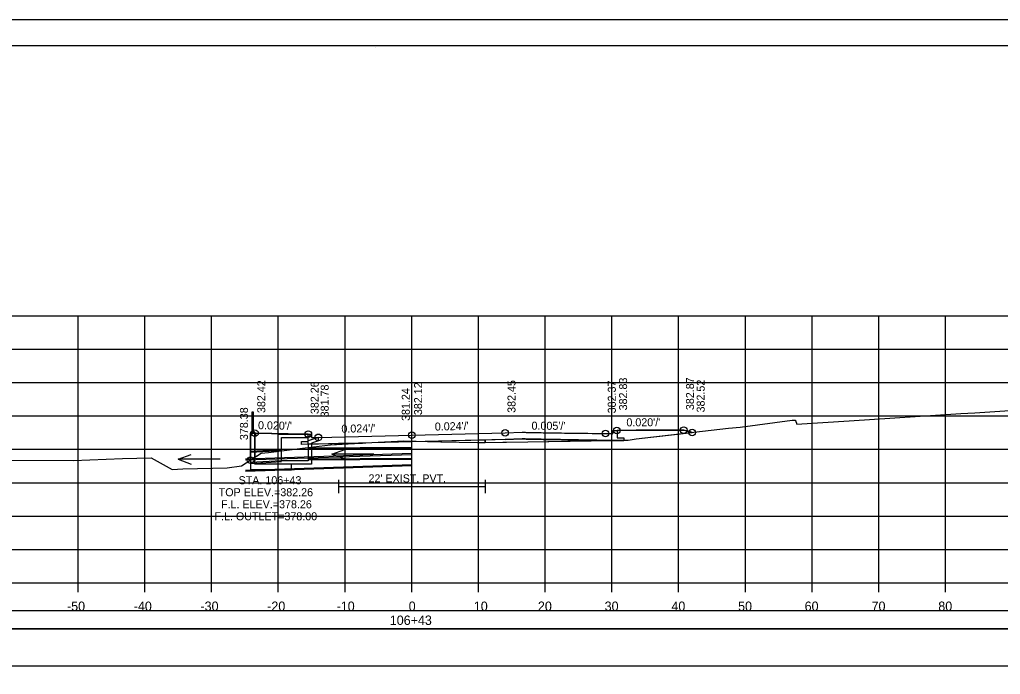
# Model space of a CAD drawing. Extents: x -37291014 to -37290680, y -936053 to -933067.
# Drawn here: x -37290901.9 to -37290754.9, y -934658 to -934559.9 of the extents above; entities that cross this region are included whole.
import ezdxf

# ---------------------------------------------------------------- set-up
doc = ezdxf.new("R2010")
doc.units = 0
for name, color, linetype in [('Default', 7, 'Continuous'), ('R_Alt Surface', 7, 'Continuous'), ('R_Axis', 7, 'Continuous'), ('R_Axis Annot', 7, 'Continuous'), ('R_Border', 7, 'Continuous'), ('R_Contours', 7, 'Continuous'), ('R_Exist Surface', 7, 'Continuous'), ('R_Fin Surface', 7, 'Continuous'), ('R_Grid', 7, 'Continuous'), ('R_No Plot', 7, 'Continuous'), ('R_Water', 7, 'Continuous'), ('R_Water Annot', 7, 'Continuous'), ('R_Xsect Elev', 7, 'Continuous'), ('R_Xsect Slope', 7, 'Continuous')]:
    doc.layers.add(name, color=color, linetype=linetype)

msp = doc.modelspace()

# ---------------------------------------------------------------- linework, layer by layer
at = {"layer": 'Default'}
for p, q in [((-37290867.02, -934621.69), (-37290867.02, -934618.69)), ((-37290867.02, -934618.69), (-37290866.85, -934618.69)), ((-37290866.85, -934618.69), (-37290866.85, -934621.69)), ((-37290867.21, -934621.71), (-37290867.27, -934621.77)), ((-37290867.27, -934621.77), (-37290867.27, -934627.37)), ((-37290866.66, -934621.69), (-37290867.21, -934621.69)), ((-37290867.21, -934621.69), (-37290867.21, -934621.71)), ((-37290866.66, -934621.71), (-37290867.21, -934621.71)), ((-37290866.66, -934621.71), (-37290866.66, -934621.69)), ((-37290866.6, -934621.77), (-37290866.66, -934621.71)), ((-37290866.6, -934626.54), (-37290866.6, -934621.77)), ((-37290861.1, -934626.54), (-37290866.6, -934626.54)), ((-37290861.1, -934627.37), (-37290861.1, -934626.54)), ((-37290861.1, -934627.37), (-37290867.27, -934627.37))]:
    msp.add_line(p, q, dxfattribs=at)
msp.add_lwpolyline([(-37290866.52, -934622.37), (-37290866.6, -934622.37), (-37290866.6, -934621.87), (-37290866.52, -934621.87), (-37290866.52, -934622.37)], dxfattribs=at)
for points in [[(-37290992.31, -934651.2), (-37290693.89, -934651.2), (-37290693.89, -934648.5), (-37290992.31, -934648.5)], [(-37290992.31, -934656.72), (-37290693.89, -934656.72), (-37290693.89, -934651.2), (-37290992.31, -934651.2)]]:
    msp.add_lwpolyline(points, close=True, dxfattribs=at)
at = {"layer": 'R_Alt Surface'}
for points in [[(-37290829.1, -934622.84), (-37290843.1, -934623.18), (-37290857.1, -934623.51), (-37290858.6, -934623.54), (-37290859.6, -934623.56), (-37290859.61, -934623.15), (-37290858.6, -934623.13), (-37290858.6, -934622.03)], [(-37290812.34, -934621.47), (-37290812.34, -934622.56), (-37290811.33, -934622.58), (-37290811.34, -934623), (-37290815.35, -934622.92)], [(-37290829.1, -934622.84), (-37290826.57, -934622.74), (-37290826.32, -934622.75), (-37290826.11, -934622.75), (-37290826.1, -934622.75), (-37290825.93, -934622.76), (-37290825.84, -934622.76), (-37290825.81, -934622.76), (-37290825.54, -934622.77), (-37290825.49, -934622.77), (-37290825.38, -934622.77), (-37290825.2, -934622.77), (-37290825.01, -934622.78), (-37290824.82, -934622.78), (-37290824.59, -934622.79), (-37290824.49, -934622.79), (-37290824.4, -934622.79), (-37290823.93, -934622.8), (-37290823.92, -934622.8), (-37290823.72, -934622.8), (-37290823.69, -934622.8), (-37290823.41, -934622.81), (-37290823.29, -934622.81), (-37290822.84, -934622.82), (-37290822.78, -934622.82), (-37290822.61, -934622.82), (-37290822.22, -934622.83), (-37290821.88, -934622.84), (-37290821.76, -934622.84), (-37290821.54, -934622.84), (-37290821.43, -934622.84), (-37290821.08, -934622.85), (-37290820.8, -934622.85), (-37290820.64, -934622.86), (-37290820.23, -934622.86), (-37290819.99, -934622.86), (-37290819.43, -934622.87), (-37290819.3, -934622.87), (-37290819.1, -934622.88), (-37290818.3, -934622.88), (-37290818.15, -934622.89), (-37290818.12, -934622.89), (-37290815.35, -934622.92)], [(-37290854.1, -934628.85), (-37290854.1, -934630.85)], [(-37290832.1, -934628.85), (-37290832.1, -934630.85)], [(-37290854.1, -934629.85), (-37290832.1, -934629.85)]]:
    msp.add_lwpolyline(points, dxfattribs=at)
at = {"layer": 'R_Axis'}
for p, q in [((-37290993.1, -934644.3), (-37290693.1, -934644.3)), ((-37290893.1, -934645.7), (-37290893.1, -934644.3)), ((-37290883.1, -934645.7), (-37290883.1, -934644.3)), ((-37290873.1, -934645.7), (-37290873.1, -934644.3)), ((-37290863.1, -934645.7), (-37290863.1, -934644.3)), ((-37290853.1, -934645.7), (-37290853.1, -934644.3)), ((-37290843.1, -934645.7), (-37290843.1, -934644.3)), ((-37290833.1, -934645.7), (-37290833.1, -934644.3)), ((-37290823.1, -934645.7), (-37290823.1, -934644.3)), ((-37290813.1, -934645.7), (-37290813.1, -934644.3)), ((-37290803.1, -934645.7), (-37290803.1, -934644.3)), ((-37290793.1, -934645.7), (-37290793.1, -934644.3)), ((-37290783.1, -934645.7), (-37290783.1, -934644.3)), ((-37290773.1, -934645.7), (-37290773.1, -934644.3)), ((-37290763.1, -934645.7), (-37290763.1, -934644.3))]:
    msp.add_line(p, q, dxfattribs=at)
at = {"layer": 'R_Border'}
for p, q in [((-37291001.1, -934563.84), (-37290684.92, -934563.84)), ((-37290848.58, -934564.1), (-37290848.58, -934564.1)), ((-37290848.58, -934564.1), (-37290848.58, -934564.1))]:
    msp.add_line(p, q, dxfattribs=at)
at = {"layer": 'R_Contours'}
for p, q in [((-37290801.07, -934621.78), (-37290801.35, -934621.7)), ((-37290866.6, -934622.37), (-37290866.6, -934625.48)), ((-37290854.1, -934623.55), (-37290850.5, -934623.36)), ((-37290850.5, -934623.36), (-37290854.1, -934623.44)), ((-37290854.1, -934623.44), (-37290854.1, -934623.55)), ((-37290854.1, -934623.55), (-37290854.1, -934623.44)), ((-37290832.1, -934622.91), (-37290840.74, -934623.12)), ((-37290829.1, -934622.84), (-37290832.1, -934622.91)), ((-37290832.1, -934623.26), (-37290832.1, -934622.91)), ((-37290832.1, -934622.91), (-37290832.1, -934623.26)), ((-37290813.02, -934622.96), (-37290815.35, -934622.92)), ((-37290811.34, -934622.93), (-37290813.02, -934622.96)), ((-37290813.02, -934622.96), (-37290811.34, -934623)), ((-37290811.34, -934623), (-37290811.34, -934622.93)), ((-37290866.6, -934625.48), (-37290867.27, -934625.91)), ((-37290866.6, -934626.54), (-37290866.6, -934625.48)), ((-37290861.1, -934626.54), (-37290866.6, -934626.54)), ((-37290861.1, -934627.37), (-37290861.1, -934626.54)), ((-37290867.27, -934627.37), (-37290861.1, -934627.37))]:
    msp.add_line(p, q, dxfattribs=at)
for points in [[(-37290866.52, -934621.88), (-37290866.52, -934622.37), (-37290866.6, -934622.37)], [(-37290858.6, -934622.03), (-37290861.6, -934621.97), (-37290866.52, -934621.88)], [(-37290854.1, -934623.44), (-37290857.1, -934623.51), (-37290858.6, -934623.54), (-37290859.6, -934623.56), (-37290859.61, -934623.15), (-37290858.6, -934623.13), (-37290858.6, -934622.03)], [(-37290801.35, -934621.7), (-37290802.35, -934621.43), (-37290802.42, -934621.43), (-37290802.43, -934621.43), (-37290803.95, -934621.43), (-37290804.11, -934621.43), (-37290804.4, -934621.43), (-37290804.44, -934621.44), (-37290806.18, -934621.44), (-37290807.2, -934621.45), (-37290807.64, -934621.45), (-37290807.73, -934621.45), (-37290808.2, -934621.45), (-37290808.31, -934621.45), (-37290809.47, -934621.45), (-37290812.15, -934621.47), (-37290812.26, -934621.47), (-37290812.34, -934621.47)], [(-37290812.34, -934621.47), (-37290812.34, -934622.56), (-37290811.33, -934622.58), (-37290811.34, -934622.93)], [(-37290811.34, -934622.93), (-37290810.65, -934622.92), (-37290809.45, -934622.75), (-37290801.07, -934621.78)], [(-37290866.6, -934625.48), (-37290865.67, -934624.87), (-37290864.57, -934624.78), (-37290859.46, -934624.13), (-37290857.83, -934623.95), (-37290855.28, -934623.61), (-37290854.1, -934623.55)], [(-37290840.74, -934623.12), (-37290838.72, -934623.18), (-37290833.25, -934623.27), (-37290832.1, -934623.26)], [(-37290832.1, -934623.26), (-37290825.72, -934623.2), (-37290813.02, -934622.96)], [(-37290815.35, -934622.92), (-37290818.12, -934622.89), (-37290818.15, -934622.89), (-37290818.3, -934622.88), (-37290819.1, -934622.88), (-37290819.3, -934622.87), (-37290819.43, -934622.87), (-37290819.99, -934622.86), (-37290820.23, -934622.86), (-37290820.64, -934622.86), (-37290820.8, -934622.85), (-37290821.08, -934622.85), (-37290821.43, -934622.84), (-37290821.54, -934622.84), (-37290821.76, -934622.84), (-37290821.88, -934622.84), (-37290822.22, -934622.83), (-37290822.61, -934622.82), (-37290822.78, -934622.82), (-37290822.84, -934622.82), (-37290823.29, -934622.81), (-37290823.41, -934622.81), (-37290823.69, -934622.8), (-37290823.72, -934622.8), (-37290823.92, -934622.8), (-37290823.93, -934622.8), (-37290824.4, -934622.79), (-37290824.49, -934622.79), (-37290824.59, -934622.79), (-37290824.82, -934622.78), (-37290825.01, -934622.78), (-37290825.2, -934622.77), (-37290825.38, -934622.77), (-37290825.49, -934622.77), (-37290825.54, -934622.77), (-37290825.81, -934622.76), (-37290825.84, -934622.76), (-37290825.93, -934622.76), (-37290826.11, -934622.75), (-37290826.32, -934622.75), (-37290826.57, -934622.74), (-37290829.1, -934622.84)], [(-37290867.27, -934625.91), (-37290867.27, -934625.92), (-37290867.27, -934627.37)]]:
    msp.add_lwpolyline(points, dxfattribs=at)
at = {"layer": 'R_Exist Surface'}
msp.add_lwpolyline([(-37290905.12, -934625.95), (-37290893.8, -934626), (-37290886.47, -934625.67), (-37290882.14, -934625.59), (-37290878.99, -934627.3), (-37290877.42, -934627.24), (-37290870.76, -934627.09), (-37290868.6, -934626.78), (-37290865.67, -934624.87), (-37290864.57, -934624.78), (-37290859.46, -934624.13), (-37290857.83, -934623.95), (-37290855.28, -934623.61), (-37290849.08, -934623.28), (-37290844.28, -934623.02), (-37290838.72, -934623.18), (-37290833.25, -934623.27), (-37290825.72, -934623.2), (-37290810.65, -934622.92), (-37290809.45, -934622.75), (-37290795.65, -934621.15), (-37290793.87, -934620.98), (-37290786.08, -934619.94), (-37290786.05, -934619.94), (-37290785.6, -934619.95), (-37290785.59, -934619.97), (-37290785.4, -934620.51), (-37290784.63, -934620.46), (-37290777.56, -934620.01), (-37290760.79, -934618.95), (-37290758.73, -934618.83), (-37290731.11, -934617.01)], dxfattribs=at)
at = {"layer": 'R_Fin Surface'}
for points in [[(-37290867.27, -934625.92), (-37290867.27, -934621.87), (-37290866.6, -934621.87), (-37290861.6, -934621.97), (-37290858.6, -934622.03), (-37290858.1, -934622.03), (-37290858.1, -934622.53), (-37290857.1, -934622.51), (-37290843.1, -934622.18), (-37290829.1, -934621.84)], [(-37290829.1, -934621.84), (-37290826.57, -934621.74), (-37290826.32, -934621.75), (-37290826.11, -934621.75), (-37290826.1, -934621.75), (-37290825.93, -934621.76), (-37290825.84, -934621.76), (-37290825.82, -934621.76), (-37290825.54, -934621.77), (-37290825.49, -934621.77), (-37290825.38, -934621.77), (-37290825.2, -934621.77), (-37290825.01, -934621.78), (-37290824.82, -934621.78), (-37290824.59, -934621.79), (-37290824.49, -934621.79), (-37290824.4, -934621.79), (-37290823.93, -934621.8), (-37290823.92, -934621.8), (-37290823.72, -934621.8), (-37290823.7, -934621.8), (-37290823.41, -934621.81), (-37290823.29, -934621.81), (-37290822.84, -934621.82), (-37290822.78, -934621.82), (-37290822.61, -934621.82), (-37290822.22, -934621.83), (-37290821.88, -934621.84), (-37290821.76, -934621.84), (-37290821.54, -934621.84), (-37290821.43, -934621.84), (-37290821.09, -934621.85), (-37290820.8, -934621.85), (-37290820.64, -934621.85), (-37290820.23, -934621.86), (-37290819.99, -934621.86), (-37290819.44, -934621.87), (-37290819.3, -934621.87), (-37290819.11, -934621.88), (-37290818.3, -934621.88), (-37290818.15, -934621.89), (-37290818.12, -934621.89), (-37290817.23, -934621.9), (-37290817.11, -934621.9), (-37290816.7, -934621.9), (-37290816.08, -934621.91), (-37290815.98, -934621.91), (-37290815.92, -934621.91), (-37290815.16, -934621.92), (-37290814.84, -934621.92), (-37290814.77, -934621.92), (-37290814.07, -934621.92), (-37290813.19, -934621.95), (-37290812.95, -934621.96), (-37290812.94, -934621.54), (-37290812.94, -934621.46), (-37290812.39, -934621.47), (-37290812.38, -934621.47), (-37290812.34, -934621.47), (-37290812.34, -934621.47), (-37290812.26, -934621.47), (-37290812.15, -934621.47), (-37290812.14, -934621.47), (-37290809.47, -934621.45), (-37290808.31, -934621.45), (-37290808.2, -934621.45), (-37290807.73, -934621.45), (-37290807.64, -934621.45), (-37290807.2, -934621.45), (-37290806.18, -934621.44), (-37290804.44, -934621.44), (-37290804.4, -934621.43), (-37290804.11, -934621.43), (-37290803.95, -934621.43), (-37290802.43, -934621.43), (-37290802.42, -934621.43), (-37290802.42, -934621.43), (-37290802.42, -934621.43), (-37290802.35, -934621.43), (-37290801.35, -934621.7), (-37290801.07, -934621.78)]]:
    msp.add_lwpolyline(points, dxfattribs=at)
at = {"layer": 'R_Grid'}
for p, q in [((-37290993.1, -934604.3), (-37290693.1, -934604.3)), ((-37290893.1, -934644.3), (-37290893.1, -934604.3)), ((-37290883.1, -934644.3), (-37290883.1, -934604.3)), ((-37290873.1, -934644.3), (-37290873.1, -934604.3)), ((-37290863.1, -934644.3), (-37290863.1, -934604.3)), ((-37290853.1, -934644.3), (-37290853.1, -934604.3)), ((-37290843.1, -934644.3), (-37290843.1, -934604.3)), ((-37290833.1, -934644.3), (-37290833.1, -934604.3)), ((-37290823.1, -934644.3), (-37290823.1, -934604.3)), ((-37290813.1, -934644.3), (-37290813.1, -934604.3)), ((-37290803.1, -934644.3), (-37290803.1, -934604.3)), ((-37290793.1, -934644.3), (-37290793.1, -934604.3)), ((-37290783.1, -934644.3), (-37290783.1, -934604.3)), ((-37290773.1, -934644.3), (-37290773.1, -934604.3)), ((-37290763.1, -934644.3), (-37290763.1, -934604.3)), ((-37290993.1, -934609.3), (-37290693.1, -934609.3)), ((-37290993.1, -934614.3), (-37290693.1, -934614.3)), ((-37290993.1, -934619.3), (-37290693.1, -934619.3)), ((-37290993.1, -934624.3), (-37290693.1, -934624.3)), ((-37290993.1, -934629.3), (-37290693.1, -934629.3)), ((-37290993.1, -934634.3), (-37290693.1, -934634.3)), ((-37290993.1, -934639.3), (-37290693.1, -934639.3)), ((-37290993.1, -934644.3), (-37290693.1, -934644.3))]:
    msp.add_line(p, q, dxfattribs=at)
at = {"layer": 'R_No Plot'}
for p, q in [((-37291013.5, -934559.94), (-37290680.17, -934559.94)), ((-37290843.1, -934624.94), (-37290868.02, -934625.78)), ((-37290862.6, -934624.37), (-37290867.27, -934624.63)), ((-37290843.1, -934624.02), (-37290858.61, -934624.12)), ((-37290862.6, -934626.2), (-37290867.27, -934626.46)), ((-37290843.1, -934625.85), (-37290858.61, -934625.95)), ((-37290843.1, -934626.77), (-37290868.02, -934627.62))]:
    msp.add_line(p, q, dxfattribs=at)
for points in [[(-37291013.51, -934559.94), (-37290680.17, -934559.94), (-37290680.17, -934773.28), (-37291013.51, -934773.28)], [(-37290767.18, -934563.84), (-37290747.56, -934563.84), (-37290747.56, -934573.72), (-37290731.45, -934573.72), (-37290708.25, -934573.72), (-37290708.25, -934598.05), (-37290684.92, -934598.05), (-37290684.92, -934769.3), (-37291001.1, -934769.3), (-37291001.1, -934563.84)]]:
    msp.add_lwpolyline(points, close=True, dxfattribs=at)
for centre in [(-37290866.6, -934621.87), (-37290858.6, -934622.03), (-37290857.1, -934622.51), (-37290843.1, -934622.18), (-37290829.1, -934621.84), (-37290829.1, -934621.84), (-37290814.07, -934621.92), (-37290812.38, -934621.47), (-37290802.35, -934621.43), (-37290801.07, -934621.78), (-37290867.27, -934625.92)]:
    msp.add_circle(centre, 0.5, dxfattribs=at)
at = {"layer": 'R_Water'}
for p, q in [((-37290863.1, -934622.03), (-37290858.35, -934622.03)), ((-37290863.1, -934623.53), (-37290863.1, -934622.03)), ((-37290858.27, -934622.2), (-37290858.6, -934622.53)), ((-37290858.27, -934622.2), (-37290858.35, -934622.03)), ((-37290862.6, -934623.53), (-37290862.6, -934622.53)), ((-37290862.6, -934622.53), (-37290858.6, -934622.53)), ((-37290857.1, -934622.51), (-37290858.6, -934623.03)), ((-37290858.6, -934623.53), (-37290858.6, -934623.03)), ((-37290857.1, -934623.04), (-37290858.1, -934623.39)), ((-37290858.1, -934623.53), (-37290858.1, -934623.39)), ((-37290843.1, -934625.11), (-37290868.02, -934625.95)), ((-37290862.6, -934624.54), (-37290867.27, -934624.8)), ((-37290843.1, -934624.19), (-37290858.61, -934624.29)), ((-37290843.1, -934626.61), (-37290868.02, -934627.45)), ((-37290862.6, -934626.04), (-37290867.27, -934626.3)), ((-37290843.1, -934625.69), (-37290858.61, -934625.79))]:
    msp.add_line(p, q, dxfattribs=at)
for points in [[(-37290858.1, -934623.53), (-37290858.1, -934626.54), (-37290860.6, -934626.54), (-37290863.1, -934626.54), (-37290863.1, -934623.53)], [(-37290858.6, -934623.53), (-37290858.6, -934626.04), (-37290860.6, -934626.04), (-37290862.6, -934626.04), (-37290862.6, -934623.53)], [(-37290857.1, -934623.04), (-37290857.1, -934622.51)]]:
    msp.add_lwpolyline(points, dxfattribs=at)
at = {"layer": 'R_Water Annot'}
for p, q in [((-37290878.11, -934625.8), (-37290876.18, -934625.1)), ((-37290855.08, -934625.03), (-37290853.15, -934624.33)), ((-37290848.79, -934625.03), (-37290855.08, -934625.03)), ((-37290855.08, -934625.03), (-37290853.15, -934625.73)), ((-37290871.82, -934625.8), (-37290878.11, -934625.8)), ((-37290878.11, -934625.8), (-37290876.18, -934626.5))]:
    msp.add_line(p, q, dxfattribs=at)
at = {"layer": 'R_Xsect Elev'}
msp.add_line((-37290843.1, -934623.05), (-37290843.1, -934613.05), dxfattribs=at)

# ---------------------------------------------------------------- texts
at = {"layer": 'R_Axis Annot'}
for s, p in [('-50', (-37290894.76, -934648.5)), ('-40', (-37290884.76, -934648.5)), ('-30', (-37290874.76, -934648.5)), ('-20', (-37290864.76, -934648.5)), ('-10', (-37290854.36, -934648.5)), ('0', (-37290843.56, -934648.5)), ('10', (-37290833.79, -934648.5)), ('20', (-37290824.19, -934648.5)), ('30', (-37290814.19, -934648.5)), ('40', (-37290804.19, -934648.5)), ('50', (-37290794.19, -934648.5)), ('60', (-37290784.22, -934648.5)), ('70', (-37290774.19, -934648.5)), ('80', (-37290764.19, -934648.5)), ('106+43', (-37290846.39, -934650.6))]:
    msp.add_text(s, height=1.4, dxfattribs=at).set_placement(p)
at = {"layer": 'R_Water'}
msp.add_text("22' EXIST. PVT.", height=1.2, dxfattribs=at).set_placement((-37290849.58, -934629.25))
at = {"layer": 'R_Water Annot'}
for s, p in [('STA. 106+43', (-37290869.05, -934629.53)), ('TOP ELEV.=382.26', (-37290872.03, -934631.33)), ('F.L. ELEV.=378.26', (-37290871.68, -934633.13)), ('F.L. OUTLET=378.00', (-37290872.66, -934634.93))]:
    msp.add_text(s, height=1.2, dxfattribs=at).set_placement(p)
at = {"layer": 'R_Xsect Elev'}
for s, rotation, p in [('382.42', 90, (-37290865.05, -934618.87)), ('382.26', 90, (-37290857.05, -934619.03)), ('381.78', 90, (-37290855.55, -934619.51)), ('382.12', 90, (-37290841.55, -934619.18)), ('382.45', 90, (-37290827.55, -934618.84)), ('382.37', 90, (-37290812.52, -934618.92)), ('382.83', 90, (-37290810.83, -934618.47)), ('382.87', 90, (-37290800.8, -934618.43)), ('382.52', 90, (-37290799.2, -934618.78)), ('381.24', 90, (-37290843.4, -934620.05)), ('378.38', 90, (-37290867.65, -934622.92)), ("0.005'/'", 359.6897, (-37290825.15, -934621.36))]:
    msp.add_text(s, height=1.2, rotation=rotation, dxfattribs=at).set_placement(p)
at = {"layer": 'R_Xsect Slope'}
for s, rotation, p in [("0.020'/'", 358.8542, (-37290866.15, -934621.28)), ("0.024'/'", 1.3748, (-37290853.63, -934621.83)), ("0.024'/'", 1.3748, (-37290839.63, -934621.5)), ("0.020'/'", 0.2211, (-37290810.93, -934620.86))]:
    msp.add_text(s, height=1.2, rotation=rotation, dxfattribs=at).set_placement(p)

doc.saveas('drawing.dxf')
